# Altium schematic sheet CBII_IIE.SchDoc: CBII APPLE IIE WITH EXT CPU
size A2; Engineer: SHOWELL; DocumentNumber: 1; Revision: 1.00; SheetNumber: 1; SheetTotal: 1
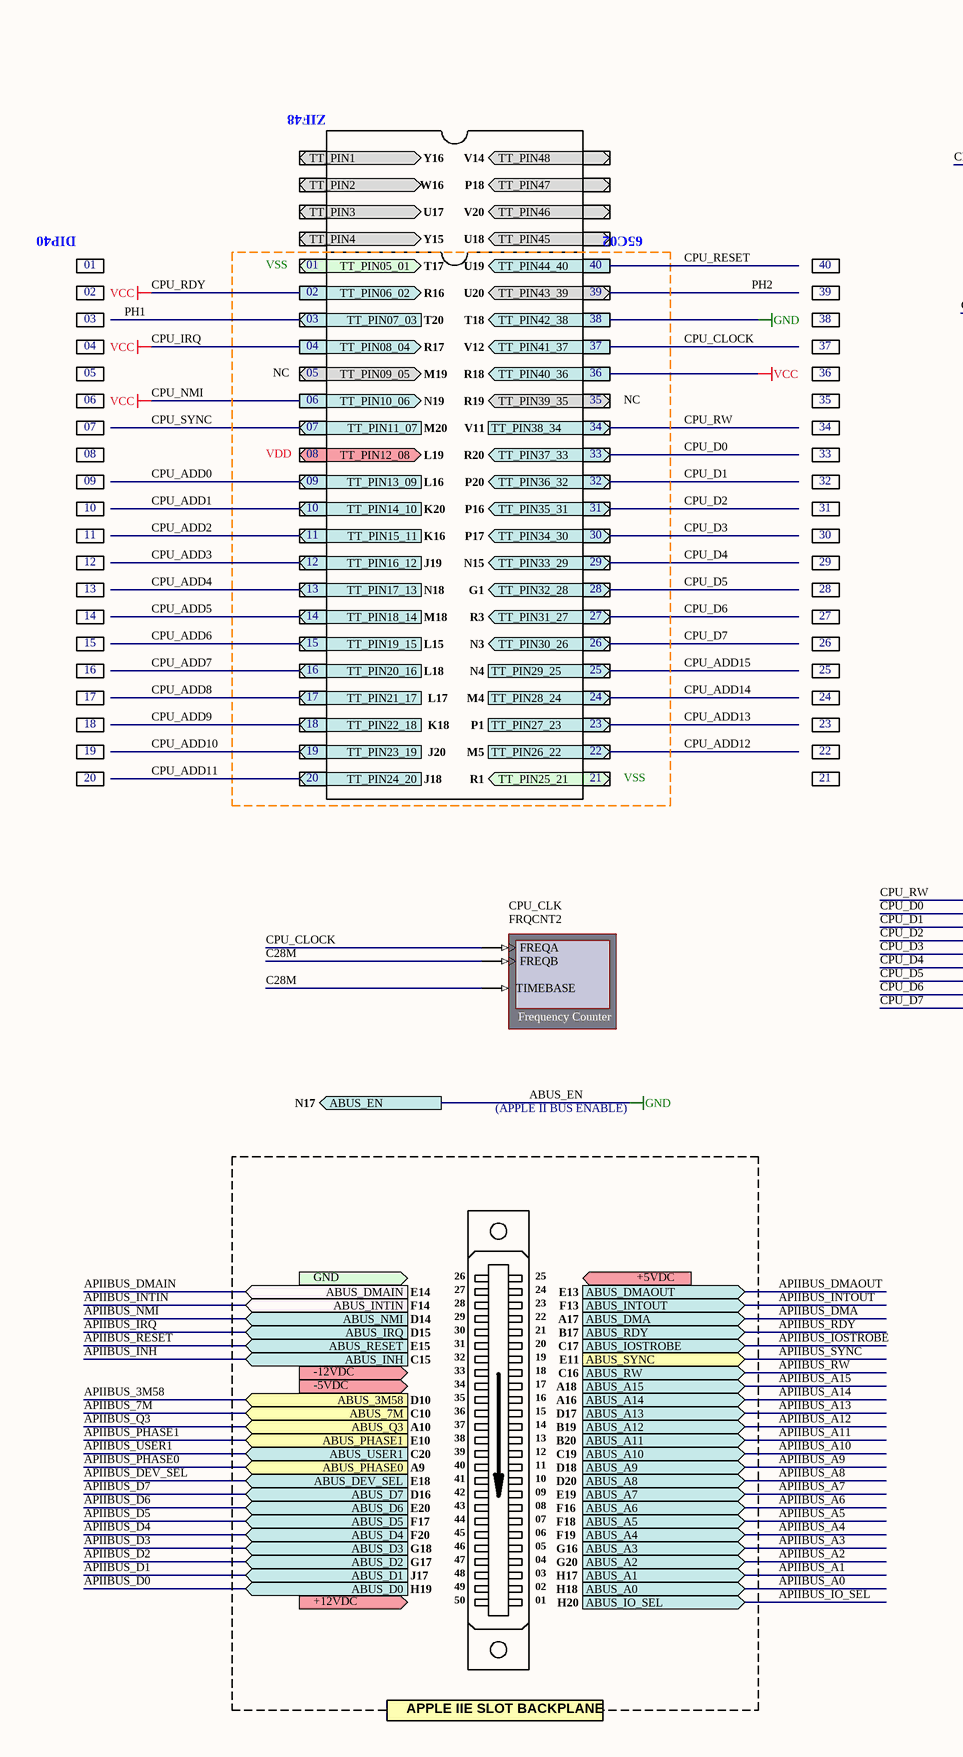
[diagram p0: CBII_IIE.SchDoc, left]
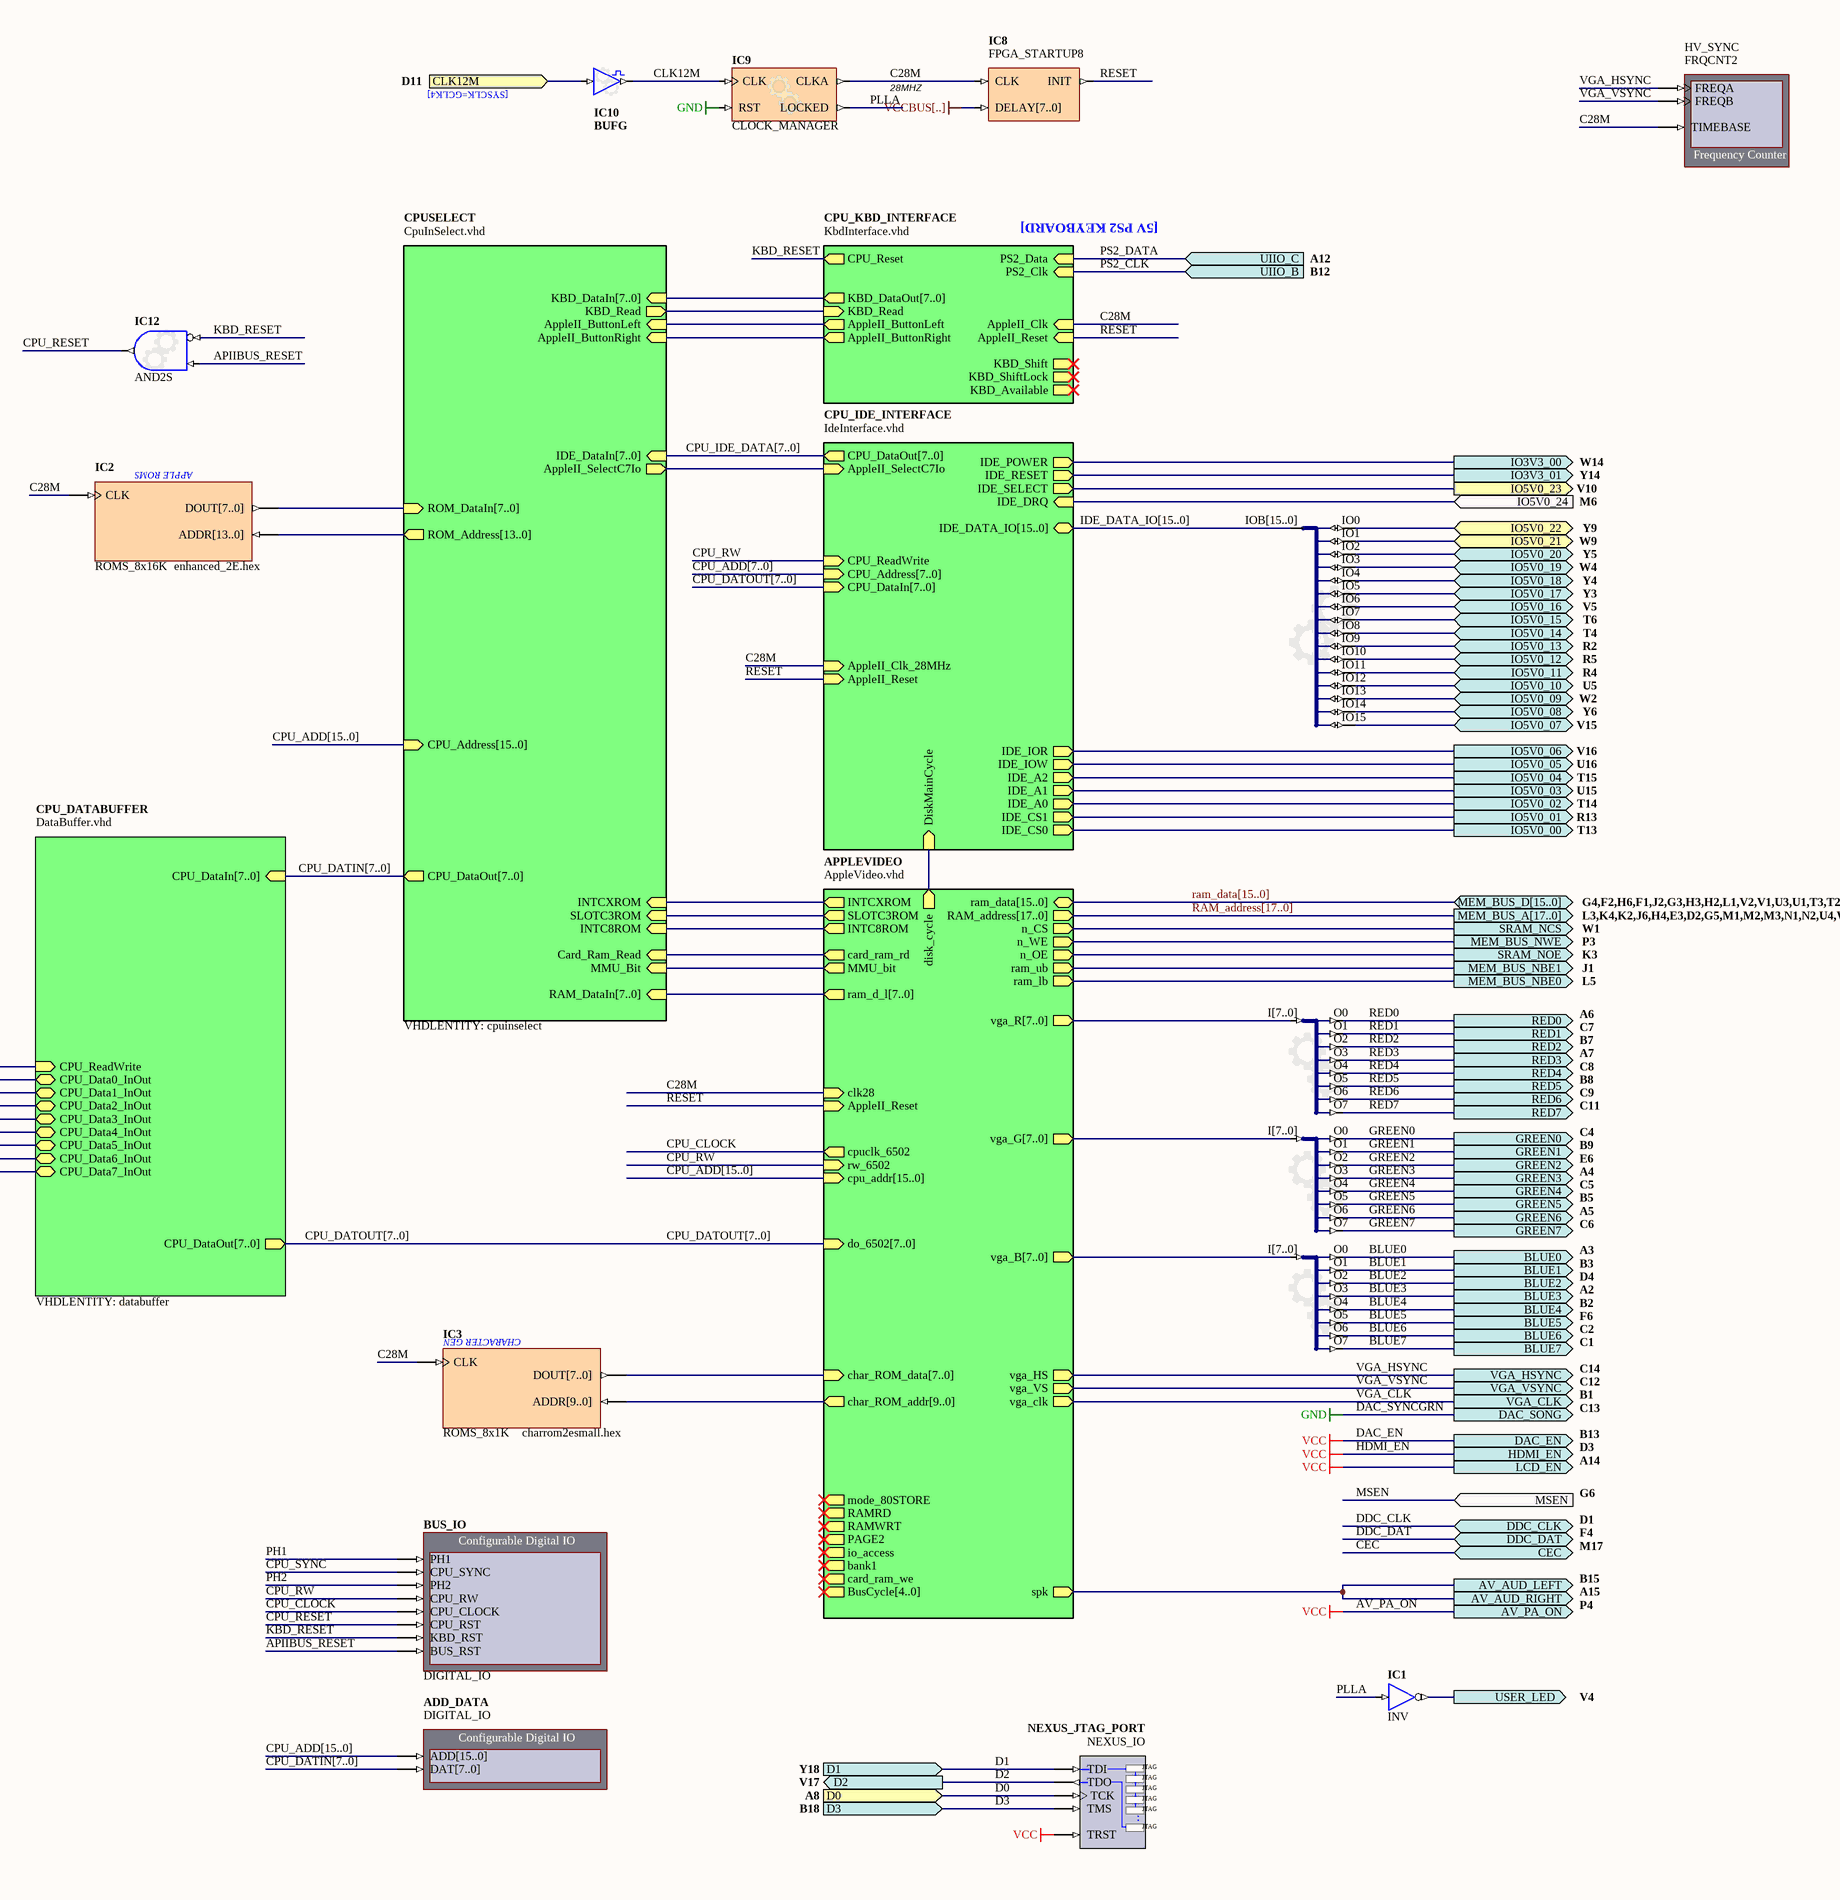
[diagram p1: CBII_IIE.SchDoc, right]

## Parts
ADD_DATA  DIGITAL_IO
BUS_IO  DIGITAL_IO
CPU_CLK  FRQCNT2
HV_SYNC  FRQCNT2
IC1  INV
IC2  ROMS_8x16K  Memory_ContentFile: enhanced_2E.hex
IC3  ROMS_8x1K  Memory_ContentFile: charrom2esmall.hex
IC4  BUS_JS  (value not drawn)
IC5  BUS_JS  (value not drawn)
IC6  BUS_JS  (value not drawn)
IC8  FPGA_STARTUP8
IC9  CLOCK_MANAGER
IC10  BUFG
IC11  BUS_JS  (value not drawn)
IC12  AND2S
NEXUS_JTAG_PORT  NEXUS_IO

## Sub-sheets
CPU_DATABUFFER = DataBuffer.vhd: CPU_Data0_InOut (bidir), CPU_Data1_InOut (bidir), CPU_Data2_InOut (bidir), CPU_Data3_InOut (bidir), CPU_Data4_InOut (bidir), CPU_Data5_InOut (bidir), CPU_Data6_InOut (bidir), CPU_Data7_InOut (bidir), CPU_DataIn[7..0] (in), CPU_DataOut[7..0] (out), CPU_ReadWrite (in)  | VHDLENTITY: databuffer
CPU_IDE_INTERFACE = IdeInterface.vhd: AppleII_Clk_28MHz (in), AppleII_Reset (in), AppleII_SelectC7Io (in), CPU_Address[7..0] (in), CPU_DataIn[7..0] (in), CPU_DataOut[7..0] (out), CPU_ReadWrite (in), DiskMainCycle (in), IDE_A0 (out), IDE_A1 (out), IDE_A2 (out), IDE_CS0 (out), IDE_CS1 (out), IDE_DATA_IO[15..0] (bidir), IDE_DRQ (in), IDE_IOR (out), IDE_IOW (out), IDE_RESET (out), IDE_SELECT (out), IDE_POWER (out)  | VHDLENTITY: ideinterface
CPU_KBD_INTERFACE = KbdInterface.vhd: AppleII_ButtonLeft (out), AppleII_ButtonRight (out), AppleII_Clk (in), AppleII_Reset (in), CPU_Reset (out), KBD_Available (out), KBD_DataOut[7..0] (out), KBD_Read (in), KBD_Shift (out), KBD_ShiftLock (out), PS2_Clk (in), PS2_Data (in)  | VHDLENTITY: kbdinterface
CPUSELECT = CpuInSelect.vhd: AppleII_ButtonLeft (in), AppleII_SelectC7Io (out), Card_Ram_Read (in), CPU_Address[15..0] (in), CPU_DataOut[7..0] (out), IDE_DataIn[7..0] (in), INTC8ROM (in), INTCXROM (in), KBD_DataIn[7..0] (in), KBD_Read (out), MMU_Bit (in), RAM_DataIn[7..0] (in), ROM_Address[13..0] (out), ROM_DataIn[7..0] (in), SLOTC3ROM (in), AppleII_ButtonRight (in)  | VHDLENTITY: cpuinselect
U_Hard_CPU_AppleVideo = AppleVideo.vhd: char_ROM_addr[9..0] (out), char_ROM_data[7..0] (in), clk28 (in), n_CS (out), n_OE (out), n_WE (out), vga_B[7..0] (out), vga_G[7..0] (out), vga_R[7..0] (out), vga_HS (out), vga_VS (out), RAM_address[17..0] (out), ram_data[15..0] (bidir), cpuclk_6502 (out), rw_6502 (in), do_6502[7..0] (in), cpu_addr[15..0] (in), disk_cycle (out), card_ram_we (out), card_ram_rd (out), bank1 (out), spk (out), MMU_bit (out), io_access (out), PAGE2 (out), INTCXROM (out), INTC8ROM (out), SLOTC3ROM (out), mode_80STORE (out), RAMRD (out), RAMWRT (out), BusCycle[4..0] (out), ram_ub (out), ram_lb (out), ram_d_l[7..0] (out), AppleII_Reset (in), vga_clk (out)  | VHDLENTITY: APPLEVIDEO

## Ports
ABUS_3M58 (in, see D10), ABUS_7M (in, see C10), ABUS_A0 (in, see H18), ABUS_A1 (in, see H17), ABUS_A2 (in, see G20), ABUS_A3 (in, see G16), ABUS_A4 (in, see F19), ABUS_A5 (in, see F18), ABUS_A6 (in, see F16), ABUS_A7 (in, see E19), ABUS_A8 (in, see D20), ABUS_A9 (in, see D18), ABUS_A10 (in, see C19), ABUS_A11 (in, see B20), ABUS_A12 (in, see B19), ABUS_A13 (in, see D17), ABUS_A14 (in, see A16), ABUS_A15 (in, see A18), ABUS_D0 (in, see H19), ABUS_D1 (in, see J17), ABUS_D2 (in, see G17), ABUS_D3 (in, see G18), ABUS_D4 (in, see F20), ABUS_D5 (in, see F17), ABUS_D6 (in, see E20), ABUS_D7 (in, see D16), ABUS_DEV_SEL (in, see E18), ABUS_DMA (in, see A17), ABUS_DMAIN (in, see E14), ABUS_DMAOUT (in, see E13), ABUS_EN (out, see N17), ABUS_INH (in, see C15), ABUS_INTIN (in, see F14), ABUS_INTOUT (in, see F13), ABUS_IO_SEL (in, see H20), ABUS_IOSTROBE (in, see C17), ABUS_IRQ (in, see D15), ABUS_NMI (in, see D14), ABUS_PHASE0 (in, see A9), ABUS_PHASE1 (in, see E10), ABUS_Q3 (in, see A10), ABUS_RDY (in, see B17), ABUS_RESET (in, see E15), ABUS_RW (in, see C16), ABUS_SYNC (in, see E11), ABUS_USER1 (in, see C20), AV_AUD_LEFT (out, see B15), AV_AUD_RIGHT (out, see A15), AV_PA_ON (out, see P4), BLUE0 (out, see A3), BLUE1 (out, see B3), BLUE2 (out, see D4), BLUE3 (out, see A2), BLUE4 (out, see B2), BLUE5 (out, see F6), BLUE6 (out, see C2), BLUE7 (out, see C1), CEC (bidir, see M17), CLK12M (in, see D11), D0 (in, see A8), D1 (in, see Y18), D2 (out, see V17), D3 (in, see B18), DAC_EN (out, see B13), DAC_SONG (out, see C13), DDC_CLK (bidir, see D1), DDC_DAT (bidir, see F4), GREEN0 (out, see C4), GREEN1 (out, see B9), GREEN2 (out, see E6), GREEN3 (out, see A4), GREEN4 (out, see C5), GREEN5 (out, see B5), GREEN6 (out, see A5), GREEN7 (out, see C6), HDMI_EN (out, see D3), IO3V3_00 (out, see W14), IO3V3_01 (out, see Y14), IO5V0_00 (out, see T13), IO5V0_01 (out, see R13), IO5V0_02 (out, see T14), IO5V0_03 (out, see U15), IO5V0_04 (out, see T15), IO5V0_05 (out, see U16), IO5V0_06 (out, see V16), IO5V0_07 (bidir, see V15), IO5V0_08 (bidir, see Y6), IO5V0_09 (bidir, see W2), IO5V0_10 (bidir, see U5), IO5V0_11 (bidir, see R4), IO5V0_12 (bidir, see R5), IO5V0_13 (bidir, see R2), IO5V0_14 (bidir, see T4), IO5V0_15 (bidir, see T6), IO5V0_16 (bidir, see V5), IO5V0_17 (bidir, see Y3), IO5V0_18 (bidir, see Y4), IO5V0_19 (bidir, see W4), IO5V0_20 (bidir, see Y5), IO5V0_21 (bidir, see W9), IO5V0_22 (bidir, see Y9), IO5V0_23 (out, see V10), IO5V0_24 (in, see M6), LCD_EN (out, see A14), MEM_BUS_A[17..0] (out, see L3,K4,K2,J6,H4,E3,D2,G5,M1,M2,M3,N1,N2,U4,W3,V6,U7,W6), MEM_BUS_D[15..0] (bidir, see G4,F2,H6,F1,J2,G3,H3,H2,L1,V2,V1,U3,U1,T3,T2,T1), MEM_BUS_NBE0 (out, see L5), MEM_BUS_NBE1 (out, see J1), MEM_BUS_NWE (out, see P3), MSEN (in, see G6), RED0 (out, see A6), RED1 (out, see C7), RED2 (out, see B7), RED3 (out, see A7), RED4 (out, see C8), RED5 (out, see B8), RED6 (out, see C9), RED7 (out, see C11), SRAM_NCS (out, see W1), SRAM_NOE (out, see K3), TT_PIN1 (bidir, see Y16), TT_PIN2 (bidir, see W16), TT_PIN3 (bidir, see U17), TT_PIN4 (bidir, see Y15), TT_PIN05_01 (in, see T17), TT_PIN06_02 (out, see R16), TT_PIN07_03 (in, see T20), TT_PIN08_04 (out, see R17), TT_PIN09_05 (bidir, see M19), TT_PIN10_06 (out, see N19), TT_PIN11_07 (in, see M20), TT_PIN12_08 (in, see L19), TT_PIN13_09 (in, see L16), TT_PIN14_10 (in, see K20), TT_PIN15_11 (in, see K16), TT_PIN16_12 (in, see J19), TT_PIN17_13 (in, see N18), TT_PIN18_14 (in, see M18), TT_PIN19_15 (in, see L15), TT_PIN20_16 (in, see L18), TT_PIN21_17 (in, see L17), TT_PIN22_18 (in, see K18), TT_PIN23_19 (in, see J20), TT_PIN24_20 (in, see J18), TT_PIN25_21 (in, see R1), TT_PIN26_22 (in, see M5), TT_PIN27_23 (in, see P1), TT_PIN28_24 (in, see M4), TT_PIN29_25 (in, see N4), TT_PIN30_26 (bidir, see N3), TT_PIN31_27 (bidir, see R3), TT_PIN32_28 (bidir, see G1), TT_PIN33_29 (bidir, see N15), TT_PIN34_30 (bidir, see P17), TT_PIN35_31 (bidir, see P16), TT_PIN36_32 (bidir, see P20), TT_PIN37_33 (bidir, see R20), TT_PIN38_34 (in, see V11), TT_PIN39_35 (bidir, see R19), TT_PIN40_36 (out, see R18), TT_PIN41_37 (out, see V12), TT_PIN42_38 (out, see T18), TT_PIN43_39 (bidir, see U20), TT_PIN44_40 (out, see U19), TT_PIN45 (bidir, see U18), TT_PIN46 (bidir, see V20), TT_PIN47 (bidir, see P18), TT_PIN48 (bidir, see V14), UIIO_B (in, see B12), UIIO_C (in, see A12), USER_LED (out, see V4), VGA_CLK (out, see B1), VGA_HSYNC (out, see C14), VGA_VSYNC (out, see C12)

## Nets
ABUS_EN: IC9.RST ; port TT_PIN42_38, port DAC_SONG, port ABUS_EN  [also labelled DAC_SYNCGRN, GND]
AV_PA_ON: NEXUS_JTAG_PORT.TRST ; port TT_PIN40_36, port TT_PIN10_06, port TT_PIN06_02, port TT_PIN08_04, port HDMI_EN, port AV_PA_ON, port DAC_EN, port LCD_EN  [also labelled CPU_IRQ, CPU_NMI, CPU_RDY, DAC_EN, HDMI_EN, VCC]
APIIBUS_RESET: BUS_IO.BUS_RST IC12.I1 ; port ABUS_RESET
AV_AUD_LEFT: port AV_AUD_LEFT, port AV_AUD_RIGHT, sheet U_Hard_CPU_AppleVideo/spk
BLUE0: IC6.O0 ; port BLUE0
BLUE1: IC6.O1 ; port BLUE1
BLUE2: IC6.O2 ; port BLUE2
BLUE3: IC6.O3 ; port BLUE3
BLUE4: IC6.O4 ; port BLUE4
BLUE5: IC6.O5 ; port BLUE5
BLUE6: IC6.O6 ; port BLUE6
BLUE7: IC6.O7 ; port BLUE7
C28M: CPU_CLK.FREQB CPU_CLK.TIMEBASE HV_SYNC.TIMEBASE IC2.CLK IC3.CLK IC8.CLK IC9.CLKA ; sheet U_Hard_CPU_AppleVideo/clk28, sheet CPU_IDE_INTERFACE/AppleII_Clk_28MHz, sheet CPU_KBD_INTERFACE/AppleII_Clk
CLK12M: IC10.I ; port CLK12M
CLK12M: IC9.CLK IC10.O  [a separate net that carries the same name]
CPU_CLOCK: BUS_IO.CPU_CLOCK CPU_CLK.FREQA ; port TT_PIN41_37, sheet U_Hard_CPU_AppleVideo/cpuclk_6502
CPU_D0: port TT_PIN37_33, sheet CPU_DATABUFFER/CPU_Data0_InOut
CPU_D1: port TT_PIN36_32, sheet CPU_DATABUFFER/CPU_Data1_InOut
CPU_D2: port TT_PIN35_31, sheet CPU_DATABUFFER/CPU_Data2_InOut
CPU_D3: port TT_PIN34_30, sheet CPU_DATABUFFER/CPU_Data3_InOut
CPU_D4: port TT_PIN33_29, sheet CPU_DATABUFFER/CPU_Data4_InOut
CPU_D5: port TT_PIN32_28, sheet CPU_DATABUFFER/CPU_Data5_InOut
CPU_D6: port TT_PIN31_27, sheet CPU_DATABUFFER/CPU_Data6_InOut
CPU_D7: port TT_PIN30_26, sheet CPU_DATABUFFER/CPU_Data7_InOut
CPU_RESET: BUS_IO.CPU_RST IC12.O ; port TT_PIN44_40
CPU_RW: BUS_IO.CPU_RW ; port TT_PIN38_34, sheet U_Hard_CPU_AppleVideo/rw_6502, sheet CPU_DATABUFFER/CPU_ReadWrite, sheet CPU_IDE_INTERFACE/CPU_ReadWrite
CPU_SYNC: BUS_IO.CPU_SYNC ; port TT_PIN11_07
D0: NEXUS_JTAG_PORT.TCK ; port D0
D1: NEXUS_JTAG_PORT.TDI ; port D1
D2: NEXUS_JTAG_PORT.TDO ; port D2
D3: NEXUS_JTAG_PORT.TMS ; port D3
GREEN0: IC5.O0 ; port GREEN0
GREEN1: IC5.O1 ; port GREEN1
GREEN2: IC5.O2 ; port GREEN2
GREEN3: IC5.O3 ; port GREEN3
GREEN4: IC5.O4 ; port GREEN4
GREEN5: IC5.O5 ; port GREEN5
GREEN6: IC5.O6 ; port GREEN6
GREEN7: IC5.O7 ; port GREEN7
IO3V3_00: port IO3V3_00, sheet CPU_IDE_INTERFACE/IDE_POWER
IO3V3_01: port IO3V3_01, sheet CPU_IDE_INTERFACE/IDE_RESET
IO5V0_00: port IO5V0_00, sheet CPU_IDE_INTERFACE/IDE_CS0
IO5V0_01: port IO5V0_01, sheet CPU_IDE_INTERFACE/IDE_CS1
IO5V0_02: port IO5V0_02, sheet CPU_IDE_INTERFACE/IDE_A0
IO5V0_03: port IO5V0_03, sheet CPU_IDE_INTERFACE/IDE_A1
IO5V0_04: port IO5V0_04, sheet CPU_IDE_INTERFACE/IDE_A2
IO5V0_05: port IO5V0_05, sheet CPU_IDE_INTERFACE/IDE_IOW
IO5V0_06: port IO5V0_06, sheet CPU_IDE_INTERFACE/IDE_IOR
IO5V0_07: IC11.IO15 ; port IO5V0_07
IO5V0_08: IC11.IO14 ; port IO5V0_08
IO5V0_09: IC11.IO13 ; port IO5V0_09
IO5V0_10: IC11.IO12 ; port IO5V0_10
IO5V0_11: IC11.IO11 ; port IO5V0_11
IO5V0_12: IC11.IO10 ; port IO5V0_12
IO5V0_13: IC11.IO9 ; port IO5V0_13
IO5V0_14: IC11.IO8 ; port IO5V0_14
IO5V0_15: IC11.IO7 ; port IO5V0_15
IO5V0_16: IC11.IO6 ; port IO5V0_16
IO5V0_17: IC11.IO5 ; port IO5V0_17
IO5V0_18: IC11.IO4 ; port IO5V0_18
IO5V0_19: IC11.IO3 ; port IO5V0_19
IO5V0_20: IC11.IO2 ; port IO5V0_20
IO5V0_21: IC11.IO1 ; port IO5V0_21
IO5V0_22: IC11.IO0 ; port IO5V0_22
IO5V0_23: port IO5V0_23, sheet CPU_IDE_INTERFACE/IDE_SELECT
IO5V0_24: port IO5V0_24, sheet CPU_IDE_INTERFACE/IDE_DRQ
KBD_RESET: BUS_IO.KBD_RST IC12.I0 ; sheet CPU_KBD_INTERFACE/CPU_Reset
MEM_BUS_NBE0: port MEM_BUS_NBE0, sheet U_Hard_CPU_AppleVideo/ram_lb
MEM_BUS_NBE1: port MEM_BUS_NBE1, sheet U_Hard_CPU_AppleVideo/ram_ub
MEM_BUS_NWE: port MEM_BUS_NWE, sheet U_Hard_CPU_AppleVideo/n_WE
PH1: BUS_IO.PH1 ; port TT_PIN07_03
PH2: BUS_IO.PH2 ; port TT_PIN43_39
PLLA: IC1.I IC9.LOCKED
PS2_CLK: port UIIO_B, sheet CPU_KBD_INTERFACE/PS2_Clk
PS2_DATA: port UIIO_C, sheet CPU_KBD_INTERFACE/PS2_Data
RED0: IC4.O0 ; port RED0
RED1: IC4.O1 ; port RED1
RED2: IC4.O2 ; port RED2
RED3: IC4.O3 ; port RED3
RED4: IC4.O4 ; port RED4
RED5: IC4.O5 ; port RED5
RED6: IC4.O6 ; port RED6
RED7: IC4.O7 ; port RED7
RESET: IC8.INIT ; sheet U_Hard_CPU_AppleVideo/AppleII_Reset, sheet CPU_IDE_INTERFACE/AppleII_Reset, sheet CPU_KBD_INTERFACE/AppleII_Reset
SRAM_NCS: port SRAM_NCS, sheet U_Hard_CPU_AppleVideo/n_CS
SRAM_NOE: port SRAM_NOE, sheet U_Hard_CPU_AppleVideo/n_OE
USER_LED: IC1.O ; port USER_LED
VGA_CLK: port VGA_CLK, sheet U_Hard_CPU_AppleVideo/vga_clk
VGA_HSYNC: HV_SYNC.FREQA ; port VGA_HSYNC, sheet U_Hard_CPU_AppleVideo/vga_HS
VGA_VSYNC: HV_SYNC.FREQB ; port VGA_VSYNC, sheet U_Hard_CPU_AppleVideo/vga_VS
(unnamed): sheet U_Hard_CPU_AppleVideo/disk_cycle, sheet CPU_IDE_INTERFACE/DiskMainCycle
(unnamed): sheet U_Hard_CPU_AppleVideo/card_ram_rd, sheet CPUSELECT/Card_Ram_Read  [a separate net that carries the same name]
(unnamed): sheet U_Hard_CPU_AppleVideo/MMU_bit, sheet CPUSELECT/MMU_Bit  [a separate net that carries the same name]
(unnamed): sheet U_Hard_CPU_AppleVideo/INTCXROM, sheet CPUSELECT/INTCXROM  [a separate net that carries the same name]
(unnamed): sheet U_Hard_CPU_AppleVideo/INTC8ROM, sheet CPUSELECT/INTC8ROM  [a separate net that carries the same name]
(unnamed): sheet U_Hard_CPU_AppleVideo/SLOTC3ROM, sheet CPUSELECT/SLOTC3ROM  [a separate net that carries the same name]
(unnamed): sheet CPU_IDE_INTERFACE/AppleII_SelectC7Io, sheet CPUSELECT/AppleII_SelectC7Io  [a separate net that carries the same name]
(unnamed): sheet CPUSELECT/AppleII_ButtonLeft, sheet CPU_KBD_INTERFACE/AppleII_ButtonLeft  [a separate net that carries the same name]
(unnamed): sheet CPUSELECT/KBD_Read, sheet CPU_KBD_INTERFACE/KBD_Read  [a separate net that carries the same name]
(unnamed): sheet CPUSELECT/AppleII_ButtonRight, sheet CPU_KBD_INTERFACE/AppleII_ButtonRight  [a separate net that carries the same name]

Not connected (* = marked no-connect by the designer): ADD_DATA ADD[15..0] DAT[7..0]; IC2 ADDR[13..0] DOUT[7..0]; IC3 ADDR[9..0] DOUT[7..0]; IC4 I[7..0]; IC5 I[7..0]; IC6 I[7..0]; IC8 DELAY[7..0]; IC11 IOB[15..0]

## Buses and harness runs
bus CPU_ADD[7..0] = sheet CPU_IDE_INTERFACE/CPU_Address[7..0]
bus CPU_ADD[15..0]
bus CPU_ADD[15..0] = sheet CPUSELECT/CPU_Address[15..0]
bus CPU_ADD[15..0] = sheet U_Hard_CPU_AppleVideo/cpu_addr[15..0]
bus CPU_DATIN[7..0]
bus CPU_DATIN[7..0] = sheet CPU_DATABUFFER/CPU_DataIn[7..0] = sheet CPUSELECT/CPU_DataOut[7..0]
bus CPU_DATOUT[7..0] = sheet CPU_DATABUFFER/CPU_DataOut[7..0] = sheet U_Hard_CPU_AppleVideo/do_6502[7..0]
bus CPU_DATOUT[7..0] = sheet CPU_IDE_INTERFACE/CPU_DataIn[7..0]
bus CPU_IDE_DATA[7..0] = sheet CPU_IDE_INTERFACE/CPU_DataOut[7..0] = sheet CPUSELECT/IDE_DataIn[7..0]
bus IDE_DATA_IO[15..0] = sheet CPU_IDE_INTERFACE/IDE_DATA_IO[15..0]
bus RAM_address[17..0] = port MEM_BUS_A[17..0] = sheet U_Hard_CPU_AppleVideo/RAM_address[17..0]
bus ram_data[15..0] = port MEM_BUS_D[15..0] = sheet U_Hard_CPU_AppleVideo/ram_data[15..0]
bus sheet CPU_KBD_INTERFACE/KBD_DataOut[7..0] = sheet CPUSELECT/KBD_DataIn[7..0]
bus sheet CPUSELECT/RAM_DataIn[7..0] = sheet U_Hard_CPU_AppleVideo/ram_d_l[7..0]

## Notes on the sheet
- [SYSCLK=GCLK4]
- 28MHZ
- [5V PS2 KEYBOARD]
- ZIF48
- DIP40
- 65C02
- 01
- 02
- VSS
- 40
- 39
- (near IC2) APPLE ROMS
- 03
- 04
- 05
- NC
- 38
- 37
- 36
- 06
- 07
- 35
- 34
- 08
- 09
- 10
- VDD
- 33
- 32
- 31
- 11
- 12
- 30
- 29
- 13
- 14
- 15
- 28
- 27
- 26
- 16
- 17
- 25
- 24
- 18
- 19
- 20
- 23
- 22
- 21
- (APPLE II BUS ENABLE)
- (near IC3) CHARACTER GEN
- GND
- +5VDC
- -12VDC
- -5VDC
- 41
- 42
- 43
- 44
- 45
- 46
- 47
- 48
- 49
- +12VDC
- 50
- APPLE IIE SLOT BACKPLANE
- Labels drawn without touching a wire or pin: VCCBUS[..]

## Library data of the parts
ADD_DATA = DIGITAL_IO: Configurable Digital IO; NEXUS_CORE: Instrument; NEXUS_JTAG_DEVICE: True; NEXUS_JTAG_ORDER: 0; ConfigurationParameters: {}Version[2.0]{}StorageType[3]{}InterfaceType[Parallel]{}SchCompWidth[140]{}Input0Name[ADD{1}15..0{2}]{}Input0Width[16]{}Input0InitValue[0]{}Input0Kind[Numeric]{}Input0NumRadix[Decimal]{}Input1Name[DAT{1}7..0{2}]{}Input1Width[8]{}Input1InitValue[0]{}Input1Kind[Numeric]{}Input1NumRadix[Decimal]{}NoOutputs[ ]{}Designator[ADD_DATA]{}InternalID[0]{}
BUS_IO = DIGITAL_IO: Configurable Digital IO; NEXUS_CORE: Instrument; NEXUS_JTAG_DEVICE: True; NEXUS_JTAG_ORDER: 0; ConfigurationParameters: {}Version[2.0]{}StorageType[3]{}InterfaceType[Parallel]{}SchCompWidth[140]{}Input0Name[PH1]{}Input0Width[1]{}Input0InitValue[0]{}Input0Kind[LEDs]{}Input0LEDStyle[Red]{}Input1Name[CPU_SYNC]{}Input1Width[1]{}Input1InitValue[0]{}Input1Kind[LEDs]{}Input1LEDStyle[Red]{}Input2Name[PH2]{}Input2Width[1]{}Input2InitValue[0]{}Input2Kind[LEDs]{}Input2LEDStyle[Red]{}Input3Name[CPU_RW]{}Input3Width[1]{}Input3InitValue[0]{}Input3Kind[LEDs]{}Input3LEDStyle[Red]{}Input4Name[CPU_CLOCK]{}Input4Width[1]{}Input4InitValue[0]{}Input4Kind[LEDs]{}Input4LEDStyle[Red]{}Input5Name[CPU_RST]{}Input5Width[1]{}Input5InitValue[0]{}Input5Kind[LEDs]{}Input5LEDStyle[Red]{}Input6Name[KBD_RST]{}Input6Width[1]{}Input6InitValue[0]{}Input6Kind[LEDs]{}Input6LEDStyle[Red]{}Input7Name[BUS_RST]{}Input7Width[1]{}Input7InitValue[0]{}Input7Kind[LEDs]{}Input7LEDStyle[Red]{}NoOutputs[ ]{}Designator[BUS_IO]{}InternalID[1]{}
CPU_CLK HV_SYNC = FRQCNT2: Frequency Counter; NEXUS_CORE: Instrument; NEXUS_JTAG_DEVICE: True; NEXUS_JTAG_ORDER: 0
IC1 = INV: Inverter; FunctionalClass: Logic Primitive; ArchiveName: GENERIC; VHDLIB_SIM: GENERIC_LIB
IC2 = ROMS_8x16K: Single Port ROM; Memory_Depth: 16384; Memory_Type: ROM_SinglePortBlock; Memory_Width: 8; Memory_ClockEdge: Rising; Nexus_Core: Memory_Program; Memory_EnablePin: False
IC3 = ROMS_8x1K: Single Port ROM; Memory_Depth: 1024; Memory_Type: ROM_SinglePortBlock; Memory_Width: 8; Memory_ClockEdge: Rising; Nexus_Core: Memory_Program; Memory_EnablePin: False
IC4-IC6 = BUS_JS: Configurable Bus Joiner/Splitter; ConfiguratorName: GENERIC_BUS_JS; ConfigurationParameters: {}Version[1.1]{}SplitterJoinerType[Splitter]{}SignalCount[8]{}SignalWidth0[1]{}GapBelow0[1000000]{}ConnectionType0[Pin]{}SignalWidth1[1]{}GapBelow1[1000000]{}ConnectionType1[Pin]{}SignalWidth2[1]{}GapBelow2[1000000]{}ConnectionType2[Pin]{}SignalWidth3[1]{}GapBelow3[1000000]{}ConnectionType3[Pin]{}SignalWidth4[1]{}GapBelow4[1000000]{}ConnectionType4[Pin]{}SignalWidth5[1]{}GapBelow5[1000000]{}ConnectionType5[Pin]{}SignalWidth6[1]{}GapBelow6[1000000]{}ConnectionType6[Pin]{}SignalWidth7[1]{}GapBelow7[1000000]{}ConnectionType7[Pin]{}ShowPinNames[True]{}
IC8 = FPGA_STARTUP8: FPGA Startup With 8 Bit Delay
IC9 = CLOCKMANAGER: Configurable Clock Manager; ConfiguratorName: GENERIC_CLOCKMANAGER; ConfigurationParameters: {}Version[1.0]{}Option_Configuration[object _1: TClockManagerPersist / VersionMajor [ 0 / VersionMinor [ 0 / InputFreq [ 24.000000000000000000 / InputName [ 'CLK' / OutputTargets [ < / item / Name [ 'CLKA' / OutFreqMin [ 56.000000000000000000 / OutFreqMax [ 56.000000000000000000 / OutPostDivider [ 1.000000000000000000 / end> / OutputDevices [ < / item / Name [ 'Spartan3' / Valid [ True / OutputActuals [ < / item / Name [ 'CLK0' / Multipler [ 1.000000000000000000 / Divider [ 1.000000000000000000 / OutFreq [ 120.000000000000000000 / OutputMap [ 1 / end / item / Name [ 'CLK90' / Multipler [ 1.000000000000000000 / Divider [ 1.000000000000000000 / OutPhase [ 90.000000000000000000 / OutFreq [ 120.000000000000000000 / OutputMap [ 2 / end / item / Name [ 'CLK180' / Multipler [ 1.000000000000000000 / Divider [ 1.000000000000000000 / OutPhase [ 180.000000000000000000 / OutFreq [ 120.000000000000000000 / OutputMap [ 3 / end / item / Name [ 'CLK270' / Multipler [ 1.000000000000000000 / Divider [ 1.000000000000000000 / OutPhase [ 270.000000000000000000 / OutFreq [ 120.000000000000000000 / OutputMap [ 4 / end / item / Name [ 'CLK2X' / Multipler [ 2.000000000000000000 / Divider [ 1.000000000000000000 / OutFreq [ 240.000000000000000000 / OutputMap [ 5 / end / item / Name [ 'CLKDV' / Multipler [ 1.000000000000000000 / Divider [ 16.000000000000000000 / OutFreq [ 7.500000000000000000 / OutputMap [ 6 / end / item / Name [ 'CLK2X180' / Multipler [ 1.000000000000000000 / Divider [ 1.000000000000000000 / OutPhase [ 180.000000000000000000 / OutFreq [ 240.000000000000000000 / OutputMap [ 7 / end / item / Name [ 'CLKFX' / Multipler [ 7.000000000000000000 / Divider [ 30.000000000000000000 / OutFreq [ 28.000000000000000000 / OutputMap [ 0 / end / item / Name [ 'CLKFX180' / Multipler [ 1.000000000000000000 / Divider [ 1.000000000000000000 / OutPhase [ 180.000000000000000000 / OutFreq [ 28.000000000000000000 / OutputMap [ 8 / end> / InternalActuals [ <> / CustomVars [ <> / end / item / Name [ 'Spartan3AN' / Valid [ True / OutputActuals [ < / item / Name [ 'CLK0' / Multipler [ 1.000000000000000000 / Divider [ 1.000000000000000000 / OutFreq [ 24.000000000000000000 / OutputMap [ 1 / end / item / Name [ 'CLK90' / Multipler [ 1.000000000000000000 / Divider [ 1.000000000000000000 / OutPhase [ 90.000000000000000000 / OutFreq [ 24.000000000000000000 / OutputMap [ 2 / end / item / Name [ 'CLK180' / Multipler [ 1.000000000000000000 / Divider [ 1.000000000000000000 / OutPhase [ 180.000000000000000000 / OutFreq [ 24.000000000000000000 / OutputMap [ 3 / end / item / Name [ 'CLK270' / Multipler [ 1.000000000000000000 / Divider [ 1.000000000000000000 / OutPhase [ 270.000000000000000000 / OutFreq [ 24.000000000000000000 / OutputMap [ 4 / end / item / Name [ 'CLK2X' / Multipler [ 2.000000000000000000 / Divider [ 1.000000000000000000 / OutFreq [ 48.000000000000000000 / OutputMap [ 5 / end / item / Name [ 'CLKDV' / Multipler [ 1.000000000000000000 / Divider [ 16.000000000000000000 / OutFreq [ 1.500000000000000000 / OutputMap [ 6 / end / item / Name [ 'CLK2X180' / Multipler [ 1.000000000000000000 / Divider [ 1.000000000000000000 / OutPhase [ 180.000000000000000000 / OutFreq [ 48.000000000000000000 / OutputMap [ 7 / end / item / Name [ 'CLKFX' / Multipler [ 7.000000000000000000 / Divider [ 3.000000000000000000 / OutFreq [ 56.000000000000000000 / OutputMap [ 0 / end / item / Name [ 'CLKFX180' / Multipler [ 1.000000000000000000 / Divider [ 1.000000000000000000 / OutPhase [ 180.000000000000000000 / OutFreq [ 56.000000000000000000 / OutputMap [ 8 / end> / InternalActuals [ <> / CustomVars [ <> / end> / MinInputFreq [ 1.000000000000000000 / MaxInputFreq [ 280.000000000000000000 / MinOutputFreq [ 18.000000000000000000 / MaxOutputFreq [ 210.000000000000000000 / MaxOutputCount [ 9 / end]{}
IC10 = BUFG: Configurable Global Clock Buffer; ConfiguratorName: GENERIC_BUFFER; ConfigurationParameters: {}Version[1.1]{}SignalCount[1]{}SignalWidth0[1]{}OutputOption0[Global Clock]{}EnableMode[None]{}ShowPinNames[False]{}
IC11 = BUS_JS: Configurable Bus Joiner/Splitter; ConfiguratorName: GENERIC_BUS_JS; ConfigurationParameters: {}Version[1.1]{}SplitterJoinerType[IO]{}SignalCount[16]{}SignalWidth0[1]{}GapBelow0[1000000]{}ConnectionType0[Pin]{}SignalWidth1[1]{}GapBelow1[1000000]{}ConnectionType1[Pin]{}SignalWidth2[1]{}GapBelow2[1000000]{}ConnectionType2[Pin]{}SignalWidth3[1]{}GapBelow3[1000000]{}ConnectionType3[Pin]{}SignalWidth4[1]{}GapBelow4[1000000]{}ConnectionType4[Pin]{}SignalWidth5[1]{}GapBelow5[1000000]{}ConnectionType5[Pin]{}SignalWidth6[1]{}GapBelow6[1000000]{}ConnectionType6[Pin]{}SignalWidth7[1]{}GapBelow7[1000000]{}ConnectionType7[Pin]{}SignalWidth8[1]{}GapBelow8[1000000]{}ConnectionType8[Pin]{}SignalWidth9[1]{}GapBelow9[1000000]{}ConnectionType9[Pin]{}SignalWidth10[1]{}GapBelow10[1000000]{}ConnectionType10[Pin]{}SignalWidth11[1]{}GapBelow11[1000000]{}ConnectionType11[Pin]{}SignalWidth12[1]{}GapBelow12[1000000]{}ConnectionType12[Pin]{}SignalWidth13[1]{}GapBelow13[1000000]{}ConnectionType13[Pin]{}SignalWidth14[1]{}GapBelow14[1000000]{}ConnectionType14[Pin]{}SignalWidth15[1]{}GapBelow15[1000000]{}ConnectionType15[Pin]{}ShowPinNames[True]{}
IC12 = GATE: Configurable Generic Gate; ConfiguratorName: GENERIC_GATE; ConfigurationParameters: {}Version[1.1]{}GateKind[AND]{}BusInput[False]{}GateInputType[Bit]{}GateOutputOption[Normal]{}BusWidth[8]{}RegisterOutputs[False]{}NegativeClockEdge[False]{}InputCount[2]{}InputInvert0[True]{}InputInvert1[False]{}
NEXUS_JTAG_PORT = NEXUS_JTAG_PORT: Soft Nexus-Chain Connector; NEXUS_JTAG_CONNECTOR: True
